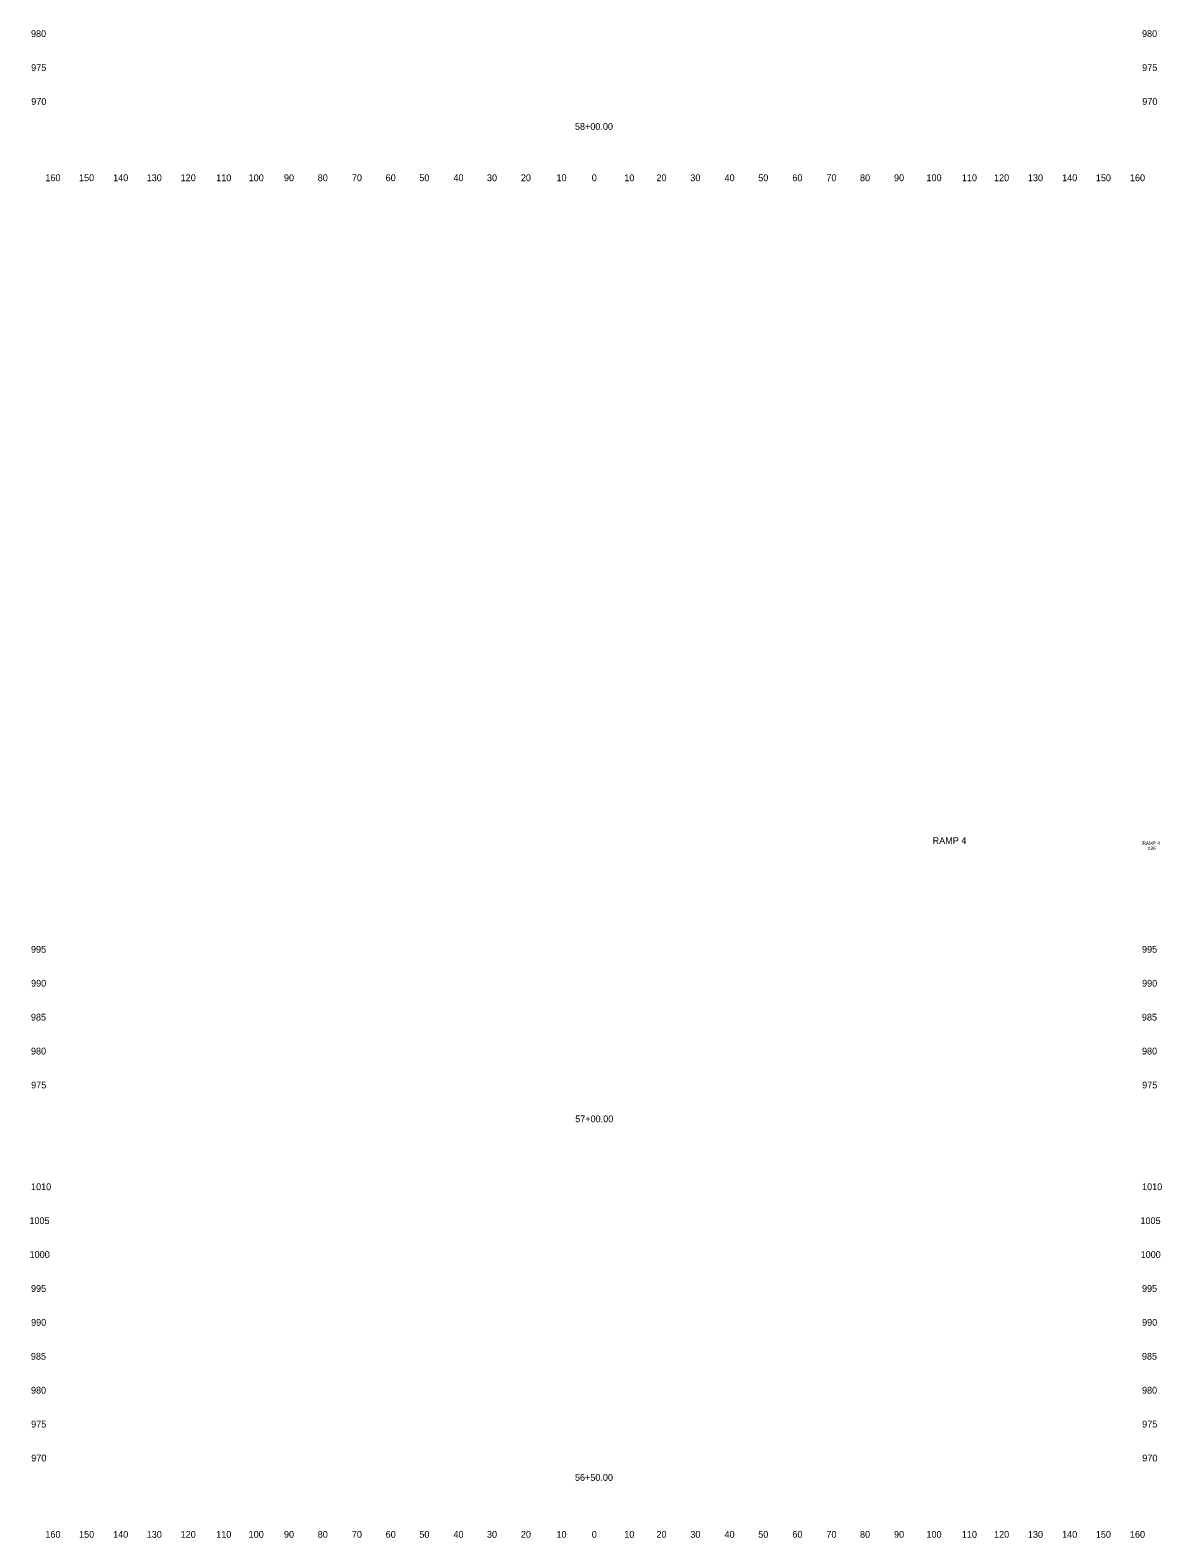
# Model space of a CAD drawing. Extents: x 4994 to 6872, y 4997 to 8804.
# Drawn here: x 6023.6 to 6357.5, y 6997.5 to 7442 of the extents above; entities that cross this region are included whole.
import ezdxf

# ---------------------------------------------------------------- set-up
doc = ezdxf.new("R2010")
doc.units = 0
for name, color, linetype in [('RD_SHT_ID', 7, 'Continuous'), ('RD_XS_TX_Offset', 7, 'Continuous'), ('RD_XS_TX_Station', 7, 'Continuous')]:
    doc.layers.add(name, color=color, linetype=linetype)

msp = doc.modelspace()

# ---------------------------------------------------------------- texts
at = {"layer": 'RD_SHT_ID'}
for s, height, p in [('RAMP 4', 2, (6289.88, 7202.06)), ('RAMP 4', 1, (6351.78, 7201.8)), ('X26', 1, (6353.26, 7200.3))]:
    msp.add_text(s, height=height, dxfattribs=at).set_placement(p)
at = {"layer": 'RD_XS_TX_Offset'}
for s, p in [('980', (6023.86, 7440)), ('980', (6351.66, 7440)), ('975', (6023.91, 7430)), ('975', (6351.71, 7430)), ('970', (6023.94, 7420)), ('970', (6351.74, 7420)), ('160', (6028.1, 7397.5)), ('150', (6038.04, 7397.5)), ('140', (6048.1, 7397.5)), ('130', (6057.99, 7397.5)), ('120', (6068.01, 7397.5)), ('110', (6078.51, 7397.5)), ('100', (6088.07, 7397.5)), ('90', (6098.5, 7397.5)), ('80', (6108.46, 7397.5)), ('70', (6118.54, 7397.5)), ('60', (6128.5, 7397.5)), ('50', (6138.43, 7397.5)), ('40', (6148.5, 7397.5)), ('30', (6158.39, 7397.5)), ('20', (6168.4, 7397.5)), ('10', (6178.91, 7397.5)), ('0', (6189.3, 7397.5)), ('0', (6189.3, 7397.5)), ('10', (6198.91, 7397.5)), ('20', (6208.4, 7397.5)), ('30', (6218.39, 7397.5)), ('40', (6228.5, 7397.5)), ('50', (6238.43, 7397.5)), ('60', (6248.5, 7397.5)), ('70', (6258.54, 7397.5)), ('80', (6268.46, 7397.5)), ('90', (6278.5, 7397.5)), ('100', (6288.07, 7397.5)), ('110', (6298.51, 7397.5)), ('120', (6308.01, 7397.5)), ('130', (6317.99, 7397.5)), ('140', (6328.1, 7397.5)), ('150', (6338.04, 7397.5)), ('160', (6348.1, 7397.5)), ('995', (6023.86, 7170)), ('995', (6351.66, 7170)), ('990', (6023.89, 7160)), ('990', (6351.69, 7160)), ('985', (6023.83, 7150)), ('985', (6351.63, 7150)), ('980', (6023.86, 7140)), ('980', (6351.66, 7140)), ('975', (6023.91, 7130)), ('975', (6351.71, 7130)), ('1010', (6023.88, 7100)), ('1010', (6351.68, 7100)), ('1005', (6023.4, 7090)), ('1005', (6351.2, 7090)), ('1000', (6023.44, 7080)), ('1000', (6351.24, 7080)), ('995', (6023.86, 7070)), ('995', (6351.66, 7070)), ('990', (6023.89, 7060)), ('990', (6351.69, 7060)), ('985', (6023.83, 7050)), ('985', (6351.63, 7050)), ('980', (6023.86, 7040)), ('980', (6351.66, 7040)), ('975', (6023.91, 7030)), ('975', (6351.71, 7030)), ('970', (6023.94, 7020)), ('970', (6351.74, 7020)), ('160', (6028.1, 6997.5)), ('150', (6038.04, 6997.5)), ('140', (6048.1, 6997.5)), ('130', (6057.99, 6997.5)), ('120', (6068.01, 6997.5)), ('110', (6078.51, 6997.5)), ('100', (6088.07, 6997.5)), ('90', (6098.5, 6997.5)), ('80', (6108.46, 6997.5)), ('70', (6118.54, 6997.5)), ('60', (6128.5, 6997.5)), ('50', (6138.43, 6997.5)), ('40', (6148.5, 6997.5)), ('30', (6158.39, 6997.5)), ('20', (6168.4, 6997.5)), ('10', (6178.91, 6997.5)), ('0', (6189.3, 6997.5)), ('0', (6189.3, 6997.5)), ('10', (6198.91, 6997.5)), ('20', (6208.4, 6997.5)), ('30', (6218.39, 6997.5)), ('40', (6228.5, 6997.5)), ('50', (6238.43, 6997.5)), ('60', (6248.5, 6997.5)), ('70', (6258.54, 6997.5)), ('80', (6268.46, 6997.5)), ('90', (6278.5, 6997.5)), ('100', (6288.07, 6997.5)), ('110', (6298.51, 6997.5)), ('120', (6308.01, 6997.5)), ('130', (6317.99, 6997.5)), ('140', (6328.1, 6997.5)), ('150', (6338.04, 6997.5)), ('160', (6348.1, 6997.5))]:
    msp.add_text(s, height=2, dxfattribs=at).set_placement(p)
at = {"layer": 'RD_XS_TX_Station'}
for s, p in [('58+00.00', (6184.35, 7412.63)), ('57+00.00', (6184.43, 7120.02)), ('56+50.00', (6184.35, 7014.28))]:
    msp.add_text(s, height=2, dxfattribs=at).set_placement(p)

doc.saveas('drawing.dxf')
